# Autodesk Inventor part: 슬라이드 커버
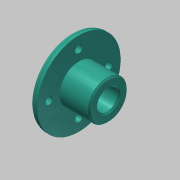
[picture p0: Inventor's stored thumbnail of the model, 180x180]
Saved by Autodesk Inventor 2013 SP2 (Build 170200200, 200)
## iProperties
Created: 2015-12
Part Number: 슬라이드 커버
Document SubType Name: Modeling
Designer: mdu
Density: 2.71 g/cm^3
Material: 알루미늄 6061
Mass: 49.5251 g
Surface Area: 80.5945 cm^2
Volume: 18.2749 cm^3
Author: mdu
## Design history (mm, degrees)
sketch "스케치1"
  geometry: L1 (-12.5, 0)-(12.5, 0); L2 (-12.5, 0)-(-12.5, 28); L3 (-12.5, 28)-(-7.5, 28); L4 (-7.5, 28)-(-7.5, 13); L5 (-7.5, 13)-(12.5, 13); L6 (12.5, 13)-(12.5, 0); 2 further points
  constraints: 12 end point, 3 perpendicular, 1 coincident, 1 horizontal, 1 midpoint, 1 parallel
  dimensions: "d1" = 56 diameter of L3 L1; "d2" = 26 diameter of L5 L1; "d5" = 5 distance of L2.end L3.end; "d32" = 20 distance of L4.end L5.end
revolve "회전1" sketch "스케치1" stored, may be unused: angle "d6" = 90 deg
sketch "스케치2" dims "d33" = 40
  geometry: 3 further points
  constraints: 2 vertical alignment, 1 coincident, 2 other
hole "구멍1" sketch "스케치2" at (0, 20) diameter "d8" = 5; stored, may be unused: countersink angle "d12" = 90 deg, drill point angle "d14" = 118 deg; dims "d9" = 6, "d10" = 8, "d11" = 4.4, "d13" = 8
hole "구멍2" diameter "d20" = 14; stored, may be unused: countersink angle "d24" = 90 deg, drill point angle "d26" = 0 deg; dims "d18" = 10, "d19" = 10, "d21" = 6, "d22" = 8, "d23" = 4.4, "d25" = 8
fillet "모깎기1" dims "d27" = 3
chamfer "모따기1" distance "d29" = 1; stored, may be unused: second distance "d30" = 2, angle "d31" = 45 deg
node "솔리드1"
pattern_circular "원형 패턴1" dims angle "d16" = 360 deg
